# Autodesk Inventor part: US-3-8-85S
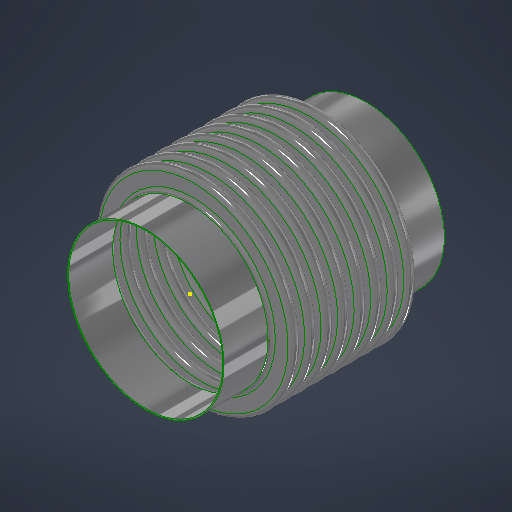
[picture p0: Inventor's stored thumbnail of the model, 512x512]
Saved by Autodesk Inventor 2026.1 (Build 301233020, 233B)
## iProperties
Category: 24 GA (0.024 THICK)
RuleStatus: InUse
Created: 2026-07
Part Number: US-3-8-85S
Project: =STOCK BELLOWS: <Stock Number><SFILL>
Material: ASTM A240-304
Description: =STOCK BELLOWS: <Stock Number>, <SID_> I.D., <SOD_> O.D., <SPLY_> PLY, <Category>, <SNET_CONS> CONS.<PITCH_><STANGENT_> TANGENT<SFILL>
Document SubType Name: Sheet Metal
Designer: LC
Stock Number: U.S-3-8-85S
Surface Area: 659.127 cm^2
Volume: 56.61 cm^3
Sheet Metal Rule: Default
Appearance: STAINLESS STEEL
NET_TUBE: 3.428
COUNTER: 1.500
PBAR: 1.214
PSET: 5.356
PLY: 2
CONS: 2
THK: 0.036
ID: 4.500
OD: 5.500
CONS_: 2
TANGENT: 0.500
PITCH: 0.375
BELLOWS_UPSET: 0.000
NET_CONS: 2
S_CONS: 0
Description_Units: 0
ID_M: 114.30 mm
OD_M: 139.70 mm
THK_M: 0.91 mm
ID_U: 4.500 in
OD_U: 5.500 in
THK_U: 0.036 in
TANGENT2: 0.500
d79: 1.000
d82: 1.000
d83: 26.000
d84: 24.000
d80: 2.571
d81: 10
SID: 2.375
SCONS_: 8
SPITCH: 0.250
SBELLOWS_UPSET: 0.000
SNET_CONS: 8
SS_CONS: 0
SCONS: 8
d174: 8
d177: 0.018
d178: 2.375
d179: 3.000
d180: 0.375
d181: 1.000
d182: 0.000
d190: 8
d191: 1
d192: 1
d193: 8
d194: 0
PART_NUMBER: U.S-3-8-85S
PRESSURE: 85
SIZE: 3.00
STANGENT_: 1.000
d214: 8
d217: 0.030
d218: 6.625
d219: 8.125
d220: 0.500
d221: 1.000
d222: 0.000
d230: 8
d231: 1
d232: 1
d233: 8
d234: 0
STANGENT: 4.000
SPLY_: 1
STHK_: 0.024
SID_: 3.500
SOD_: 4.500
SPITCH_: 0.375
STANGENT__: 1.000
SBELLOWS_UPSET_: 0.000
SDIFF_TAN: 1.000
TAN_TO_TAN: 0.750 in
d252: 2
d275: 2
d287: 0.050
d289: 0.500
d290: 0.000
d263: 2
d265: 1
d268: 2
d269: 0
d286: 2
d288: 1
d291: 2
d292: 0
SOD_NECK: 3 9/16
CFILL: .
SFILL: .
PITCH_: =, <SPITCH_> PITCH,
SREROLL: 0.750
MATTABLE: 20 GA (0.036 THICK)
MESH: ,
CSECT: 2
Author: LC
Keywords: 20 GA (0.036 THICK)
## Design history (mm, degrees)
sketch "Sketch2"
  geometry: L1 (0, -183.595)-(0, 600.956) reference; L2 (58.979, 0)-(57.15, 0); L3 (60.446, -1.467)-(66.554, -1.467); L4 (60.446, -3.296)-(66.554, -3.296); L5 (66.554, -8.058)-(60.446, -8.058); L6 (66.554, -6.229)-(60.446, -6.229); L7 (58.979, -9.525)-(57.15, -9.525); L8 (60.446, 0)-(60.446, -9.525); L9 (66.554, -4.762)-(69.85, -4.763); L10 (57.15, 0)-(57.15, -9.525); L11 (20.376, 102.841)-(20.376, 101.926); L12 (58.262, 488.877)-(58.262, 349.177); L13 (58.262, 479.352)-(58.262, 339.652); L14 (93.133, -58.817)-(93.133, -71.517); L15 (118.746, -66.401)-(118.746, -66.401); L16 (66.554, -6.229)-(66.554, -8.058); L17 (60.446, -6.229)-(60.446, -8.058); L18 (60.446, -7.144)-(66.554, -7.144); L19 (69.85, 0)-(69.85, -9.525); L20 (-66.554, -6.229)-(-66.554, -8.058); L21 (-66.554, -1.467)-(-60.446, -1.467); L22 (-66.554, -3.296)-(-60.446, -3.296); L23 (-60.446, -6.229)-(-66.554, -6.229); L24 (-66.554, -7.144)-(-60.446, -7.144); L25 (-60.446, -8.058)-(-66.554, -8.058); L26 (-60.446, -6.229)-(-60.446, -8.058); L27 (-57.15, -2.522)-(-57.15, -12.047); L28 (-60.446, -4.763)-(-57.15, -4.763); L29 (-66.554, 3.828)-(-66.554, -9.525); L30 (-68.021, 0)-(-69.85, 0); L31 (-69.85, 0)-(-69.85, -9.525); L32 (-68.021, -9.525)-(-69.85, -9.525); A1 r 1.467 centre (60.446, 0) between (58.979, 0) and (60.446, -1.467); A2 r 3.296 centre (60.446, 0) between (57.15, 0) and (60.446, -3.296); A3 r 3.296 centre (66.554, -4.762) between (66.554, -8.058) and (66.554, -1.467); A4 r 1.467 centre (66.554, -4.762) between (66.554, -6.229) and (66.554, -3.296); A5 r 1.467 centre (60.446, -9.525) between (60.446, -8.058) and (58.979, -9.525); A6 r 3.296 centre (60.446, -9.525) between (60.446, -6.229) and (57.15, -9.525); A7 r 2.381 centre (66.554, -4.762) between (66.554, -7.144) and (68.936, -4.762); A8 r 2.381 centre (60.446, -9.525) between (60.446, -7.144) and (58.064, -9.525); A9 r 1.467 centre (-66.554, -9.525) between (-66.554, -8.058) and (-68.021, -9.525); A10 r 1.467 centre (-60.446, -4.763) between (-60.446, -6.229) and (-60.446, -3.296); A11 r 2.381 centre (-60.446, -4.763) between (-60.446, -7.144) and (-58.064, -4.763); A12 r 3.296 centre (-60.446, -4.763) between (-60.446, -8.058) and (-60.446, -1.467); A13 r 2.381 centre (-66.554, -9.525) between (-66.554, -7.144) and (-68.936, -9.525); A14 r 3.296 centre (-66.554, -9.525) between (-66.554, -6.229) and (-69.85, -9.525); A15 r 1.467 centre (-66.554, 0) between (-68.021, 0) and (-66.554, -1.467); A16 r 3.296 centre (-66.554, 0) between (-69.85, 0) and (-66.554, -3.296); 10 further points
  constraints: 62 end point, 38 point on circle, 20 tangent, 16 centre point, 12 parallel, 9 midpoint, 7 vertical, 6 coincident, 6 concentric, 6 point on line, 4 equal radius, 4 perpendicular, 3 horizontal, 1 collinear, 1 horizontal alignment, 10 other
  dimensions: "THK" = 0.9144 distance of L11.start L11.end; "ID" = 114.3 distance of L11.end point (20.376, -12.374); "OD" = 139.7 distance of L12.start L12.end; "PITCH" = 9.525 distance of L12.start L13.start; "TANGENT" = 12.7 distance of L14.start L14.end; "BELLOWS_UPSET" = 0 distance of L15.start L15.end; "d43" = 114.3 diameter of L10 L1 (= ID); "d44" = 139.7 diameter of L9.end L1 (= OD); "d45" = 1.8288 distance between parallel lines of L5 L6 (computed from THK, PLY); "d46" = 3.29565 radius of A3 (computed from PITCH, THK, PLY); "UPSET_PITCH" = 9.525 distance of L2.end L7.end (derived); "SIDEWALL_ANGLE" = 0 deg angle of L3 L9 (derived); "CON_GAP" = 2.9337 distance of point (60.446, -6.229) point (60.446, -3.296) (derived); "TAN1" = 3.74046 dimension on A8 (derived); "TAN2" = 3.74046 dimension on A7 (derived); "LEG1" = 6.1087 distance of L18.start L18.end (derived); "d278" = 1.8288 distance between parallel lines of L25 L23 (derived); "d279" = 3.29565 radius of A12 (derived); "d280" = 9.525 distance of L30.end L31.end (derived); "d281" = 360 deg dimension on L21 L28 (derived); "d282" = 2.9337 distance of point (-66.554, -6.229) point (-66.554, -3.296) (derived); "d283" = 3.74046 dimension on A13 (derived); "d284" = 3.74046 dimension on A11 (derived); "d285" = 6.1087 distance of L24.start L24.end (derived); "d293" = 114.3 diameter of L27 L1 (derived); "d294" = 139.7 diameter of L31 L1 (derived)
  node "Sketch Rectangular Pattern1" dims "d31" = 25.4, "ID" = 114.3
  node "Sketch Rectangular Pattern2" dims "d39" = 25.4, "PITCH" = 9.525
revolve "CONS" stored, may be unused: angle "d48" = 90 deg
node "BELLOW MIDPLANE"
pattern_linear "Rectangular Pattern2" dims "d52" = 9.525 (= UPSET_PITCH)
sketch "Sketch5"
  geometry: C1 r 58.979 at (0, 0) reference; C2 r 57.15 at (0, 0) reference
extrude "TANGENT" new body sketch "Sketch5" distance "d53" = 12.7 (= TANGENT); taper "d54" = 0 deg
revolve "SAMETAN" stored, may be unused: angle "d65" = 90 deg
revolve "DIFFTAN" stored, may be unused: angle "d70" = 90 deg
sketch "Sketch9"
  geometry: L1 (58.391, 0)-(-58.391, 0) reference; L2 (0, -17.78)-(0, 17.78) reference; L3 (41.708, 0)-(-41.708, 0); L4 (41.708, -11.906)-(41.708, 11.906); L5 (29.008, -11.906)-(29.008, 11.906); L6 (15.418, 11.906)-(15.418, -11.906); L7 (-29.008, -11.906)-(-29.008, 11.906); L8 (-41.708, -11.906)-(-41.708, 11.906); L9 (40.914, -11.906)-(40.914, 11.906); L10 (41.708, -11.906)-(40.914, -11.906); L11 (41.708, 11.906)-(40.914, 11.906); L12 (15.815, 11.906)-(15.022, 11.906); L13 (15.022, 11.906)-(15.022, -11.906); L14 (15.022, -11.906)-(15.815, -11.906); L15 (15.815, -11.906)-(15.815, 11.906); L16 (-15.815, 11.906)-(-15.815, -11.906); L17 (-15.418, 11.906)-(-15.418, -11.906); L18 (-15.815, -11.906)-(-15.022, -11.906); L19 (-15.022, -11.906)-(-15.022, 11.906); L20 (-15.022, 11.906)-(-15.815, 11.906); L21 (-41.708, -11.906)-(-40.914, -11.906); L22 (-40.914, -11.906)-(-40.914, 11.906); L23 (-40.914, 11.906)-(-41.708, 11.906); L24 (-41.708, 11.906)-(-41.708, -11.906); L25 (41.708, -0.397)-(-41.708, -0.397); L26 (-41.708, -0.397)-(-41.708, 0.397); L27 (-41.708, 0.397)-(41.708, 0.397); L28 (41.708, 0.397)-(41.708, -0.397); L29 (-41.708, 11.906)-(41.708, 11.906); L30 (41.708, 11.906)-(41.708, 12.7); L31 (41.708, 12.7)-(-41.708, 12.7); L32 (-41.708, 12.7)-(-41.708, 11.906); L33 (41.708, -11.906)-(-41.708, -11.906); L34 (-41.708, -11.906)-(-41.708, -12.7); L35 (-41.708, -12.7)-(41.708, -12.7); L36 (41.708, -12.7)-(41.708, -11.906); 30 further points
  constraints: 68 end point, 13 midpoint, 13 parallel, 8 horizontal, 7 perpendicular, 6 equal length, 3 point on line, 2 vertical, 14 other
  dimensions: "d115" = 23.8125 distance of L4.start L4.end (derived); "d116" = 12.7 distance between parallel lines of L4 L5 (derived); "d117" = 13.58962 distance between parallel lines of L5 L6 (derived); "d125" = 44.42645 distance between parallel lines of L7 L6 (derived); "d127" = 12.7 distance between parallel lines of L8 L7 (derived); "d128" = 26.28962 distance between parallel lines of L6 L4 (derived); "d130" = 83.41607 distance between parallel lines of L8 L4 (derived); "RULER_THK" = 0.79375 distance between parallel lines of L4 L9; "d135" = 0.79375 distance of L13.end L14.end (derived); "d138" = 30.83684 distance of L13.end L16.end (derived); "d143" = 0.79375 distance of L22.end L8.end (derived); "d144" = 0.79375 distance between parallel lines of L27 L25 (derived)
extrude "RULER" join sketch "Sketch9" distance "d149" = 0.79375 (derived); taper "d150" = 0 deg
extrude "BARS" join sketch "Sketch9" distance "d151" = 0.79375 (derived); taper "d152" = 0 deg
pattern_linear "Rectangular Pattern4" dims "d155" = 30.83684 (derived)
sketch "Sketch13"
  geometry: L1 (93.149, -52.467)-(93.149, -77.867); L2 (45.06, 0)-(44.45, 0); L3 (45.06, -9.525)-(44.45, -9.525); L4 (54.464, -7.449)-(47.136, -7.449); L5 (54.464, -6.839)-(47.136, -6.839); L6 (54.464, -4.762)-(57.15, -4.762); L7 (47.136, -2.076)-(54.464, -2.076); L8 (47.136, 0)-(47.136, -9.525); L9 (44.45, 0)-(44.45, -9.525); L10 (58.254, -360.964)-(58.254, -475.264); L11 (58.254, -370.489)-(58.254, -484.789); L12 (58.254, -389.539)-(58.254, -503.839); L13 (58.254, -399.064)-(58.254, -513.364); L14 (58.254, -408.589)-(58.254, -522.889); L15 (58.254, -418.114)-(58.254, -532.414); L16 (58.254, -427.639)-(58.254, -541.939); L17 (58.254, -380.014)-(58.254, -494.314); L18 (20.376, 102.536)-(20.376, 101.926); L19 (47.136, -2.686)-(54.464, -2.686); L20 (0, -654.548)-(0, 228.539) reference; L21 (-23.752, 0)-(142.514, 0) reference; A1 r 2.076 centre (47.136, 0) between (45.06, 0) and (47.136, -2.076); A2 r 2.076 centre (47.136, -9.525) between (47.136, -7.449) and (45.06, -9.525); A3 r 2.686 centre (47.136, -9.525) between (47.136, -6.839) and (44.45, -9.525); A4 r 2.076 centre (54.464, -4.762) between (54.464, -6.839) and (54.464, -2.686); A5 r 2.686 centre (54.464, -4.762) between (54.464, -7.449) and (54.464, -2.076); A6 r 2.686 centre (47.136, 0) between (44.45, 0) and (47.136, -2.686); 6 further points; 1 other entity
  constraints: 38 end point, 15 point on circle, 9 tangent, 6 centre point, 6 parallel, 5 vertical alignment, 4 point on line, 4 vertical, 3 coincident, 3 concentric, 2 collinear, 2 equal radius, 1 horizontal, 1 perpendicular, 23 other
  dimensions: "SBELLOWS_UPSET_" = 0 distance of point (118.762, -66.401) point (118.762, -66.401); "STOTAL_THK_BELLOW__" = 0.6096 distance between parallel lines of L4 L5 (derived); "d224" = 2.68605 radius of A5 (derived); "d225" = 9.525 distance of L2.end L3.end (derived); "SSIDEWALL_ANGLE_" = 0 deg angle of L7 L6 (derived); "SSCON_GAP_" = 4.1529 distance of point (47.136, -6.839) point (47.136, -2.686) (derived); "d235" = 88.9 diameter of L9 L20 (derived); "d236" = 114.3 diameter of L6.end L20 (derived)
  node "Sketch Rectangular Pattern4" dims "d228" = 25.4
  node "Sketch Rectangular Pattern5" dims "d229" = 25.4
revolve "SBELLOW" stored, may be unused: angle "d197" = 90 deg
pattern_linear "Rectangular Pattern5" dims "d204" = 9.525 (derived)
revolve "STANGENT" stored, may be unused: angle "d240" = 90 deg
revolve "SSAMETAN" stored, may be unused: angle "d241" = 90 deg
revolve "SDIFFTAN" stored, may be unused: angle "d246" = 90 deg
revolve "INVCON" stored, may be unused: angle "d295" = 90 deg
pattern_linear "Rectangular Pattern6" dims "d298" = 9.525 (derived)
revolve "INVTANGENT" stored, may be unused: angle "d302" = 90 deg
revolve "INVSAMETAN" stored, may be unused: angle "d307" = 90 deg
revolve "INVDIFFTAN" stored, may be unused: angle "d312" = 90 deg
sketch "ID BELLOW MOUNT CALC"
  geometry: L1 (44.45, 0)-(38.1, 0); L2 (38.1, 0)-(38.1, 12.7); L3 (38.1, 12.7)-(44.45, 12.7); L4 (44.45, 12.7)-(44.45, 0); L5 (36.513, 12.7)-(34.684, 12.7); L6 (34.684, 12.7)-(34.684, 0); L7 (34.684, 0)-(36.513, 0); L8 (36.513, 0)-(36.513, 12.7); L9 (0, -2.54)-(0, 15.24) reference; L10 (-8.89, 0)-(53.34, 0) reference; 1 further point
  constraints: 16 end point, 5 parallel, 2 collinear, 2 horizontal, 2 perpendicular
  dimensions: "d314" = 12.7 distance of L5.end L6.end (derived); "d315" = 1.8288 distance of L5.start L5.end (derived); "IG" = 1.5875 distance between parallel lines of L2 L8; "PIPE_OD" = 88.9 diameter of L4 L9; "PIPE_WALL" = 6.35 distance of L2.end L3.end; "ID_MT_BELLOW" = 69.3674 diameter of L6 L9 (derived)
revolve "CFILL" stored, may be unused: angle "d320" = 90 deg
pattern_linear "Rectangular Pattern7" dims "d323" = 9.525 (derived)
revolve "SFILL" stored, may be unused: angle "d324" = 90 deg
pattern_linear "Rectangular Pattern8" dims "d327" = 9.525 (derived)
node "STOCK BELLOW MIDPLANE"
sketch "Sketch21"
  geometry: L1 (0, -100.013)-(0, 100.013) reference; L2 (-100.013, 0)-(100.013, 0) reference; L3 (-0.099, 71.437)-(0.099, 71.437); L4 (0.099, 71.437)-(0.099, 55.562); L5 (0.099, 55.562)-(-0.099, 55.562); L6 (-0.099, 55.562)-(-0.099, 71.437); C1 r 55.562 at (0, 0); C2 r 71.437 at (0, 0); 3 further points
  constraints: 8 end point, 2 centre point, 2 coincident, 2 parallel, 2 tangent, 1 horizontal, 1 perpendicular, 1 other
  dimensions: "d329" = 111.125 diameter of C1 (derived); "d330" = 142.875 diameter of C2 (derived); "d331" = 0.19844 distance of L3.start L3.end
extrude "CLAMSHELL" cut sketch "Sketch21" extent not by distance; stored distance "d332" = 0; taper "d333" = 0 deg
pattern_circular "Circular Pattern1" dims angle "d335" = 180 deg (derived)
node "BELLOW"
sketch "Sketch6"
  geometry: L1 (-19.05, 58.979)-(-6.35, 58.979); L2 (-6.35, 58.979)-(-6.35, 57.15); L3 (-6.35, 57.15)-(-19.05, 57.15); L4 (-19.05, 57.15)-(-19.05, 58.979); L5 (2.54, 0)-(-59.69, 0) reference; L6 (-38.1, -108.388)-(-38.1, 156.601) reference; 1 further point
  constraints: 8 end point, 2 parallel, 1 horizontal, 1 perpendicular
  dimensions: "d61" = 12.7 distance of L2.end L3.end (derived); "d62" = 1.8288 distance of L1.end L2.end (derived); "d63" = 114.3 diameter of L3 L5 (derived); "d64" = 19.05 distance between parallel lines of L4 L6 (derived)
sketch "Sketch12"
  geometry: 1 further point
sketch "Sketch14"
  geometry: L1 (-25.4, 45.06)-(0, 45.06); L2 (0, 45.06)-(0, 44.45); L3 (0, 44.45)-(-25.4, 44.45); L4 (-25.4, 44.45)-(-25.4, 45.06); L5 (5.08, 0)-(-30.48, 0) reference; L6 (0, -8.89)-(0, 53.34) reference; 1 further point
  constraints: 8 end point, 2 parallel, 1 collinear, 1 horizontal, 1 perpendicular
  dimensions: "d237" = 0.6096 distance of L3.end L1.start (derived); "d238" = 88.9 diameter of L3 L5 (derived); "d239" = 25.4 distance of L1.start L1.end (derived); "SOD_NECK" = 90.1192 diameter of L1 L5 (derived)
sketch "Sketch15"
  geometry: L1 (-8.89, 0)-(53.34, 0) reference; L2 (44.45, -76.2)-(45.06, -76.2); L3 (45.06, -76.2)-(45.06, -101.6); L4 (45.06, -101.6)-(44.45, -101.6); L5 (44.45, -101.6)-(44.45, -76.2); L6 (0, -124.46)-(0, 35.56) reference; 1 further point
  constraints: 8 end point, 2 parallel, 1 horizontal, 1 perpendicular
  dimensions: "d205" = 25.4 distance of L4.end L2.start (derived); "d206" = 0.6096 distance of L3.end L4.end (derived); "d207" = 88.9 diameter of L5 L6 (derived); "d208" = 76.2 distance between parallel lines of L1 L2 (derived)
node "TANGENT_"
node "SAME_TAN"
sketch "Sketch8"
  geometry: L1 (58.979, -19.05)-(57.15, -19.05); L2 (57.15, -19.05)-(57.15, -31.75); L3 (57.15, -31.75)-(58.979, -31.75); L4 (58.979, -31.75)-(58.979, -19.05); L5 (0, -40.64)-(0, 21.59) reference; L6 (-108.388, 0)-(156.601, 0) reference; 1 further point
  constraints: 8 end point, 2 parallel, 1 horizontal, 1 perpendicular
  dimensions: "d66" = 114.3 diameter of L2 L5 (derived); "TOTAL_THK_BELLOW" = 1.8288 distance of L2.end L3.end (derived); "d68" = 19.05 distance between parallel lines of L1 L6 (derived); "d69" = 12.7 distance of L1.end L2.end (derived)
node "DIFF_TAN"
node "Sketch Rectangular Pattern3" dims "d138" = 30.83684 (derived), "d141" = 25.4
node "SBELLOW_"
node "STANGENT_"
node "SSAME_TAN"
sketch "Sketch16"
  geometry: L1 (45.06, -76.2)-(44.45, -76.2); L2 (44.45, -76.2)-(44.45, -101.6); L3 (44.45, -101.6)-(45.06, -101.6); L4 (45.06, -101.6)-(45.06, -76.2); L5 (0, -124.46)-(0, 35.56) reference; L6 (-8.89, 0)-(53.34, 0) reference; 1 further point
  constraints: 8 end point, 2 parallel, 1 horizontal, 1 perpendicular
  dimensions: "SDIFF_TAN" = 25.4 distance of L3.end L1.start; "d243" = 0.6096 distance of L2.end L3.end (derived); "d244" = 76.2 distance between parallel lines of L1 L6 (derived); "d245" = 88.9 diameter of L2 L5 (derived)
node "SDIFF_TAN"
body "Solid15"
sketch "Sketch17"
  geometry: L1 (69.85, 12.7)-(68.021, 12.7); L2 (68.021, 12.7)-(68.021, 0); L3 (68.021, 0)-(69.85, 0); L4 (69.85, 0)-(69.85, 12.7); L5 (0, -2.54)-(0, 15.24) reference; L6 (-13.97, 0)-(83.82, 0) reference; 2 further points
  constraints: 8 end point, 2 parallel, 1 horizontal, 1 midpoint, 1 perpendicular, 1 point on line
  dimensions: "INVTANGENT" = 12.7 distance of L3.end L1.start (derived); "d300" = 1.8288 distance of L1.start L1.end (derived); "d301" = 139.7 diameter of L4 L5 (derived)
body "Solid16"
sketch "Sketch18"
  geometry: L1 (69.85, -19.05)-(68.021, -19.05); L2 (68.021, -19.05)-(68.021, -31.75); L3 (68.021, -31.75)-(69.85, -31.75); L4 (69.85, -31.75)-(69.85, -19.05); L5 (-13.97, 0)-(83.82, 0) reference; L6 (0, -40.64)-(0, 21.59) reference; 1 further point
  constraints: 8 end point, 2 parallel, 1 horizontal, 1 perpendicular
  dimensions: "d303" = 19.05 distance between parallel lines of L1 L5 (derived); "d304" = 12.7 distance of L3.end L1.start (derived); "d305" = 1.8288 distance of L2.end L3.end (derived); "d306" = 139.7 diameter of L4 L6 (derived)
body "Solid17"
sketch "Sketch19"
  geometry: L1 (69.85, -19.05)-(68.021, -19.05); L2 (68.021, -19.05)-(68.021, -31.75); L3 (68.021, -31.75)-(69.85, -31.75); L4 (69.85, -31.75)-(69.85, -19.05); L5 (0, -40.64)-(0, 21.59) reference; L6 (-13.97, 0)-(83.82, 0) reference; 1 further point
  constraints: 8 end point, 2 parallel, 1 horizontal, 1 perpendicular
  dimensions: "d308" = 12.7 distance of L1.end L2.end (derived); "d309" = 139.7 diameter of L4 L5 (derived); "d310" = 1.8288 distance of L2.end L3.end (derived); "d311" = 19.05 distance between parallel lines of L1 L6 (derived)
body "Solid18"
body "Solid19"
body "Solid20"
other parameters: "BMPL" = -38.1, "PSET" = 136.0424 (computed from OD, THK, PLY) [user parameter], "PBAR" = 30.83684 (= 0.570796 x PITCH + OD - ID) [user parameter; used in 1 equation term], "COUNTER" = 15 [user parameter], "NET_TUBE" = 87.07367 (computed from CONS_, PBAR, TANGENT) [user parameter], "S_CONS" = 0 [user parameter; used in 1 equation term], "ID_M" = 114.3 (= ID) [user parameter], "OD_M" = 139.7 (= OD) [user parameter], "THK_M" = 0.9144 (= THK) [user parameter], "ID_U" = 114.3 (= ID) [user parameter], "OD_U" = 139.7 (= OD) [user parameter], "THK_U" = 0.9144 (= THK) [user parameter], "D_UNITS" = 0 [user parameter], "TANGENT2" = 12.7 [user parameter], "TAN_TO_TAN" = 19.05 [user parameter], "OD_NECK" = 117.9576 [user parameter], "d79" = 25.4, "d80" = 65.29823 [user parameter], "d82" = 25.4, "d83" = 660.4, "d84" = 609.6, "sa_0" = 4, "FRAME_THK" = 0.79375 [user parameter], "CON_FLAT" = 13.58962 [user parameter], "SID" = 60.325 [user parameter], "SPITCH" = 6.35 [user parameter], "STANGENT_" = 25.4 [user parameter], "SBELLOWS_UPSET" = 0 [user parameter], "SS_CONS" = 0 [user parameter], "STAN_TO_TAN_" = 76.2 [user parameter], "d100" = 0.6096 [user parameter], "d191" = 25.4 [user parameter], "d194" = 0 [user parameter], "STANGENT" = 101.6 [user parameter], "d234" = 0 [user parameter], "SUPSET_PITCH_" = 9.525 [user parameter], "d269" = 0 [user parameter], "d287" = 1.27, "d289" = 12.7, "d290" = 0, "d292" = 0 [user parameter], "Thickness" = 3.048 (derived), "KFactor" = 4.4, "BendRadius" = 3.048 (derived), "BendReliefWidth" = 3.048 (derived), "BendReliefDepth" = 1.524 (derived), "CornerReliefSize" = 12.192 (derived), "SeamGap" = 0.00508, "MinimumRemnant" = 6.096 (derived), "TransitionRadius" = 3.048 (derived), "JacobiRadiusSize" = 3.048 (derived), "GapSize" = 3.048 (derived), "SREROLL" = 19.05 [user parameter], "CUR_STK_PITCH" = 9.525 [user parameter], "d328" = -38.1 (derived), "CSECTDEG" = 180 deg [user parameter]
